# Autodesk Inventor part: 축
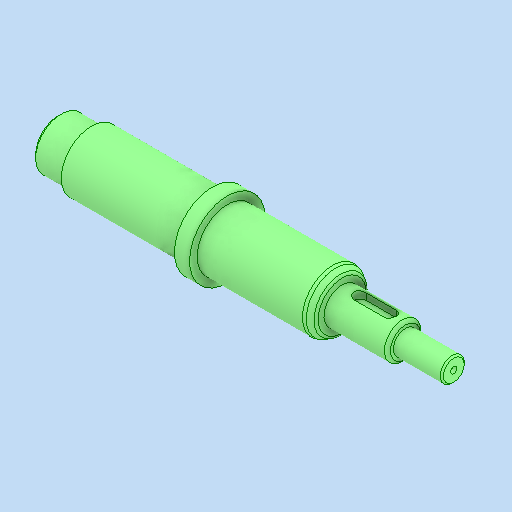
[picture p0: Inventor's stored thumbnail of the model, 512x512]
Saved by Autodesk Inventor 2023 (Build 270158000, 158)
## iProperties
Created: 2024-11
Part Number: 축
Material: 강철, 탄소
Document SubType Name: Modeling
Designer: asung
Density: 7.85 g/cm^3
Appearance: 기본값
Author: jhkim
Sending System: Autodesk Inventor 2025
Preprocessor: ST-DEVELOPER v20
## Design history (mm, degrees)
node "축1"
node "솔리드2"
node "솔리드1"
